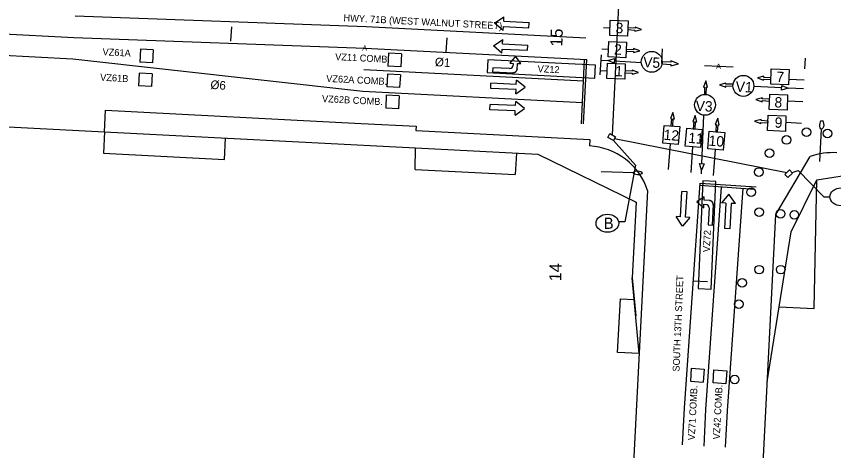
# Model space of a CAD drawing. Extents: x 0 to 1361828, y 0 to 1470398.
# Drawn here: x 683277 to 683656, y 734825.2 to 735026.6 of the extents above; entities that cross this region are included whole.
import ezdxf

# ---------------------------------------------------------------- set-up
doc = ezdxf.new("R2010")
doc.units = 0
for name, color, linetype in [('$', 7, 'Continuous'), ('090338 Base_ROW 3 - R_Horz Alg', 7, 'Continuous'), ('MOT Stage 1', 7, 'Continuous'), ('MOT Stage 1 Lanes', 7, 'Continuous'), ('R_Horz Alg Station', 7, 'Continuous'), ('R_TYPE_A_CURB', 7, 'Continuous'), ('RW-EX', 7, 'Continuous'), ('RW-PR', 7, 'Continuous'), ('SIGNAL-EX', 7, 'Continuous'), ('SIGNAL-PLAN VIEW LABLES', 7, 'Continuous'), ('SIGNAL-PR', 7, 'Continuous'), ('TITEXT', 7, 'Continuous'), ('Video-Zones-pr', 7, 'Continuous')]:
    doc.layers.add(name, color=color, linetype=linetype)

# ---------------------------------------------------------------- blocks, each defined once
blk = doc.blocks.new('SARROW_195')
at = {"layer": 'MOT Stage 1'}
for p, q in [((0, 0), (-6, 0)), ((0, -29.42), (0, 0)), ((-6, -29.42), (-6, 0)), ((-6, -29.42), (-11, -29.42)), ((-3, -39.81), (-11, -29.42)), ((5, -29.42), (-3, -39.81)), ((5, -29.42), (0, -29.42))]:
    blk.add_line(p, q, dxfattribs=at)
blk = doc.blocks.new('SARROW_196')
at = {"layer": 'MOT Stage 1'}
for p, q in [((0, 0), (-6, 0)), ((0, -29.42), (0, 0)), ((-6, -29.42), (-6, 0)), ((-6, -29.42), (-11, -29.42)), ((-3, -39.81), (-11, -29.42)), ((5, -29.42), (-3, -39.81)), ((5, -29.42), (0, -29.42))]:
    blk.add_line(p, q, dxfattribs=at)
blk = doc.blocks.new('SARROW_197')
at = {"layer": 'MOT Stage 1'}
for p, q in [((-6, -29.42), (-6, 0)), ((0, 0), (-6, 0)), ((0, -29.42), (0, 0)), ((-6, -29.42), (-11, -29.42)), ((-3, -39.81), (-11, -29.42)), ((5, -29.42), (-3, -39.81)), ((5, -29.42), (0, -29.42))]:
    blk.add_line(p, q, dxfattribs=at)
blk = doc.blocks.new('SARROW_198')
at = {"layer": 'MOT Stage 1'}
for p, q in [((-6, -29.42), (-6, 0)), ((0, 0), (-6, 0)), ((0, -29.42), (0, 0)), ((-6, -29.42), (-11, -29.42)), ((-3, -39.81), (-11, -29.42)), ((5, -29.42), (-3, -39.81)), ((5, -29.42), (0, -29.42))]:
    blk.add_line(p, q, dxfattribs=at)
blk = doc.blocks.new('SARROW_203')
at = {"layer": 'MOT Stage 1'}
for p, q in [((-6, -29.42), (-6, 0)), ((0, 0), (-6, 0)), ((0, -29.42), (0, 0)), ((-6, -29.42), (-11, -29.42)), ((-3, -39.81), (-11, -29.42)), ((5, -29.42), (-3, -39.81)), ((5, -29.42), (0, -29.42))]:
    blk.add_line(p, q, dxfattribs=at)
blk = doc.blocks.new('SARROW_204')
at = {"layer": 'MOT Stage 1'}
for p, q in [((-6, -29.42), (-6, 0)), ((0, 0), (-6, 0)), ((0, -29.42), (0, 0)), ((-6, -29.42), (-11, -29.42)), ((-3, -39.81), (-11, -29.42)), ((5, -29.42), (-3, -39.81)), ((5, -29.42), (0, -29.42))]:
    blk.add_line(p, q, dxfattribs=at)
blk = doc.blocks.new('BAREL_1730')
at = {"layer": 'MOT Stage 1'}
blk.add_circle((0, 0.01), 2.88, dxfattribs=at)
blk = doc.blocks.new('BAREL_1731')
at = {"layer": 'MOT Stage 1'}
blk.add_circle((0, 0.01), 2.88, dxfattribs=at)
blk = doc.blocks.new('BAREL_1732')
at = {"layer": 'MOT Stage 1'}
blk.add_circle((0, 0.01), 2.88, dxfattribs=at)
blk = doc.blocks.new('BAREL_1733')
at = {"layer": 'MOT Stage 1'}
blk.add_circle((0, 0.01), 2.88, dxfattribs=at)
blk = doc.blocks.new('BAREL_1734')
at = {"layer": 'MOT Stage 1'}
blk.add_circle((0, 0.01), 2.88, dxfattribs=at)
blk = doc.blocks.new('BAREL_1735')
at = {"layer": 'MOT Stage 1'}
blk.add_circle((0, 0.01), 2.88, dxfattribs=at)
blk = doc.blocks.new('BAREL_1736')
at = {"layer": 'MOT Stage 1'}
blk.add_circle((0, 0.01), 2.88, dxfattribs=at)
blk = doc.blocks.new('BAREL_1737')
at = {"layer": 'MOT Stage 1'}
blk.add_circle((0, 0.01), 2.88, dxfattribs=at)
blk = doc.blocks.new('BAREL_1738')
at = {"layer": 'MOT Stage 1'}
blk.add_circle((0, 0.01), 2.88, dxfattribs=at)
blk = doc.blocks.new('BAREL_1739')
at = {"layer": 'MOT Stage 1'}
blk.add_circle((0, 0.01), 2.88, dxfattribs=at)
blk = doc.blocks.new('BAREL_1740')
at = {"layer": 'MOT Stage 1'}
blk.add_circle((0, 0.01), 2.88, dxfattribs=at)
blk = doc.blocks.new('BAREL_1741')
at = {"layer": 'MOT Stage 1'}
blk.add_circle((0, 0.01), 2.88, dxfattribs=at)
blk = doc.blocks.new('BAREL_1742')
at = {"layer": 'MOT Stage 1'}
blk.add_circle((0, 0.01), 2.88, dxfattribs=at)
blk = doc.blocks.new('BAREL_1743')
at = {"layer": 'MOT Stage 1'}
blk.add_circle((0, 0.01), 2.88, dxfattribs=at)

msp = doc.modelspace()

# ---------------------------------------------------------------- linework, layer by layer
at = {"layer": '$'}
for p, q in [((683547.74, 734999.56), (683548.38, 735008.82)), ((683642.77, 735007.23), (683642.46, 735002.24))]:
    msp.add_line(p, q, dxfattribs=at)
at = {"layer": 'MOT Stage 1'}
for points in [[(683509.26, 735002.33), (683509.25, 735002.01), (683509.35, 735004.76), (683510.95, 735004.7), (683508.51, 735008.11), (683505.83, 735004.89), (683507.43, 735004.83), (683507.4, 735004)], [(683505.74, 735002.46), (683497.89, 735002.75), (683497.82, 735000.83)], [(683497.82, 735000.83), (683507.59, 735000.47), (683507.27, 735000.48)], [(683598.36, 734941.28), (683598.68, 734941.27), (683595.93, 734941.39), (683596, 734942.99), (683592.57, 734940.57), (683595.77, 734937.87), (683595.84, 734939.47), (683596.68, 734939.43)], [(683599.78, 734929.83), (683600.21, 734939.6), (683600.19, 734939.28)], [(683598.21, 734937.76), (683597.86, 734929.91), (683599.78, 734929.83)]]:
    msp.add_lwpolyline(points, dxfattribs=at)
for centre, radius, start, end in [((683505.8, 735004.06), 1.6, 267.8614, 357.8614), ((683507.34, 735002.4), 1.92, 267.8614, 357.8614), ((683596.61, 734937.83), 1.6, 357.5178, 87.5178), ((683598.27, 734939.36), 1.92, 357.5178, 87.5178)]:
    msp.add_arc(centre, radius, start, end, dxfattribs=at)
at = {"layer": 'MOT Stage 1 Lanes'}
for p, q in [((683123.62, 735026.19), (683303.69, 735016.89)), ((683304.21, 735026.87), (683439.13, 735021.9)), ((683439.13, 735021.9), (683541.04, 735016.68)), ((683123.1, 735016.21), (683303.18, 735006.9)), ((683303.69, 735016.89), (683438.61, 735011.92)), ((683438.61, 735011.92), (683541.52, 735006.64)), ((683303.18, 735006.9), (683437.59, 734991.94)), ((683538.99, 734976.8), (683540.52, 735006.69)), ((683539.99, 734976.73), (683541.52, 735006.64)), ((683438.1, 735001.93), (683540.01, 734996.7)), ((683437.59, 734991.94), (683539.5, 734986.71)), ((683585.91, 734827.88), (683586.78, 734844.88))]:
    msp.add_line(p, q, dxfattribs=at)
for points in [[(683586.78, 734844.88), (683594.07, 734949.32), (683620.04, 734947.51)], [(683594, 734948.32), (683619.33, 734946.56)], [(683595.89, 734827.37), (683596.76, 734844.27), (683603.97, 734947.63)], [(683605.88, 734826.85), (683606.74, 734843.67), (683613.95, 734946.93)]]:
    msp.add_lwpolyline(points, dxfattribs=at)
at = {"layer": 'R_Horz Alg Station'}
for points in [[(683376.69, 735021.79), (683376.35, 735015.13)], [(683476.56, 735016.64), (683476.22, 735009.99)], [(683576.43, 735011.52), (683576.09, 735004.86)], [(683596.02, 735003.84), (683609.34, 735003.16)], [(683590.9, 734903.97), (683597.56, 734903.63)]]:
    msp.add_lwpolyline(points, dxfattribs=at)
at = {"layer": 'R_TYPE_A_CURB'}
msp.add_lwpolyline([(683564.16, 734940.5), (683564.4, 734940.38), (683562.6, 734905.43), (683564.2, 734887.82)], dxfattribs=at)
at = {"layer": 'RW-EX'}
for p, q in [((683436.82, 734976.96), (683462.39, 734975.65)), ((683462.39, 734975.65), (683462.29, 734973.65)), ((683462.29, 734973.65), (683542.86, 734969.52)), ((683542.86, 734969.52), (683542.71, 734966.52)), ((683629.19, 734934.75), (683645.1, 734961.68)), ((683569.69, 734945.89), (683545.76, 734479.81)), ((683605.66, 734476.49), (683629.19, 734934.75))]:
    msp.add_line(p, q, dxfattribs=at)
msp.add_lwpolyline([(682968.24, 735001.18), (682967.74, 734991.19), (683067.68, 734986.03), (683317.82, 734973.1), (683318.3, 734983.09), (683436.82, 734976.96)], dxfattribs=at)
for centre, radius, start, end in [((683541.17, 734936.56), 30, 18.1182, 87.0636), ((683655.68, 734930.43), 33, 86.7989, 108.7102)]:
    msp.add_arc(centre, radius, start, end, dxfattribs=at)
at = {"layer": 'RW-PR'}
for p, q in [((683317.82, 734973.1), (683317.34, 734963.11)), ((683373.51, 734960.21), (683374.03, 734970.19)), ((683461.97, 734955.65), (683462.1, 734965.65)), ((683317.34, 734963.11), (683373.51, 734960.21)), ((683508.87, 734963.25), (683508.35, 734953.27)), ((683461.97, 734955.65), (683508.35, 734953.27)), ((683646.98, 734891.08), (683648.18, 734950.88)), ((683555.81, 734870.72), (683557.1, 734895.7)), ((683557.1, 734895.7), (683563.52, 734895.37)), ((683630.75, 734891.91), (683646.98, 734891.08)), ((683565.8, 734870.21), (683555.81, 734870.72))]:
    msp.add_line(p, q, dxfattribs=at)
for points in [[(683317.82, 734973.1), (683462.1, 734965.65), (683518.85, 734962.74)], [(683518.85, 734962.74), (683564.4, 734940.38), (683562.6, 734905.43)], [(683648.18, 734950.88), (683683.55, 734956.41), (683823.33, 734948.59), (683952.62, 734938.86), (684206.41, 734924.66)], [(683625.21, 734857.15), (683636.29, 734926.68), (683648.18, 734950.88)], [(683565.8, 734870.21), (683562.6, 734905.43)]]:
    msp.add_lwpolyline(points, dxfattribs=at)
at = {"layer": 'SIGNAL-EX'}
for points in [[(683553.48, 734971.62), (683557.44, 735053.56)], [(683553.94, 734969.07), (683564.03, 734957.59)], [(683554.4, 734969.91), (683634.28, 734954.17)], [(683636.75, 734954.19), (683639.53, 734955.17)]]:
    msp.add_lwpolyline(points, dxfattribs=at)
for points in [[(683552.26, 734972.26), (683554.89, 734970.83), (683553.94, 734969.07), (683551.3, 734970.5)], [(683633.41, 734953.33), (683635.56, 734955.41), (683636.95, 734953.98), (683634.8, 734951.89)]]:
    msp.add_lwpolyline(points, close=True, dxfattribs=at)
at = {"layer": 'SIGNAL-PLAN VIEW LABLES'}
for points in [[(683552.13, 735017.78), (683552.38, 735024.91), (683560.64, 735024.62), (683560.39, 735017.42)], [(683551.42, 735007.8), (683551.67, 735014.93), (683559.93, 735014.65), (683559.68, 735007.45)], [(683551.34, 735006.17), (683554.36, 735007.04), (683554.22, 735004.96)], [(683550.85, 734997.82), (683551.1, 735004.95), (683559.35, 735004.66), (683559.1, 734997.46)], [(683626.81, 734995.16), (683627.06, 735002.29), (683635.31, 735002), (683635.06, 734994.8)], [(683634.84, 734993.33), (683631.82, 734992.45), (683631.95, 734994.53)], [(683626.1, 734983.45), (683626.35, 734990.58), (683634.6, 734990.3), (683634.35, 734983.1)], [(683625.37, 734973.63), (683625.62, 734980.76), (683633.88, 734980.47), (683633.63, 734973.27)], [(683583.86, 734967.24), (683576.75, 734967.85), (683577.45, 734976.08), (683584.63, 734975.47)], [(683594.29, 734965.88), (683587.18, 734966.49), (683587.88, 734974.72), (683595.06, 734974.1)], [(683604.72, 734964.52), (683597.61, 734965.13), (683598.32, 734973.36), (683605.49, 734972.74)], [(683594.76, 734955.33), (683593.84, 734958.34), (683595.92, 734958.24)]]:
    msp.add_lwpolyline(points, close=True, dxfattribs=at)
for points in [[(683549.26, 735021.51), (683552.26, 735021.34)], [(683563.84, 735020.29), (683563.81, 735019.79), (683566.81, 735020.56), (683563.91, 735021.63), (683563.88, 735021.13), (683560.53, 735021.3), (683560.48, 735020.46), (683563.84, 735020.29)], [(683560.48, 735020.46), (683563.84, 735020.29), (683563.81, 735019.79), (683566.81, 735020.56), (683563.91, 735021.63), (683563.88, 735021.13), (683560.53, 735021.3)], [(683548.55, 735011.54), (683551.55, 735011.37)], [(683563.13, 735010.31), (683563.1, 735009.81), (683566.1, 735010.58), (683563.2, 735011.66), (683563.17, 735011.15), (683559.82, 735011.33), (683559.77, 735010.49), (683563.13, 735010.31)], [(683559.77, 735010.49), (683563.13, 735010.31), (683563.1, 735009.81), (683566.1, 735010.58), (683563.2, 735011.66), (683563.17, 735011.15), (683559.82, 735011.33)], [(683548.3, 735006.34), (683551.34, 735006.17)], [(683554.29, 735006), (683566.79, 735005.3)], [(683580.46, 735004.34), (683580.43, 735003.74), (683584.02, 735004.66), (683580.55, 735005.95), (683580.51, 735005.35), (683576.49, 735005.56), (683576.44, 735004.55), (683580.46, 735004.34)], [(683576.44, 735004.55), (683580.46, 735004.34), (683580.43, 735003.74), (683584.02, 735004.66), (683580.55, 735005.95), (683580.51, 735005.35), (683576.49, 735005.56)], [(683547.98, 735001.55), (683550.97, 735001.38)], [(683562.55, 735000.33), (683562.52, 734999.83), (683565.52, 735000.6), (683562.62, 735001.67), (683562.59, 735001.17), (683559.24, 735001.34), (683559.19, 735000.5), (683562.55, 735000.33)], [(683559.19, 735000.5), (683562.55, 735000.33), (683562.52, 734999.83), (683565.52, 735000.6), (683562.62, 735001.67), (683562.59, 735001.17), (683559.24, 735001.34)], [(683597.01, 734993.79), (683597.52, 734993.76), (683596.73, 734996.75), (683595.67, 734993.85), (683596.17, 734993.83), (683596.02, 734990.47), (683596.86, 734990.43), (683597.01, 734993.79)], [(683596.86, 734990.43), (683597.01, 734993.79), (683597.52, 734993.76), (683596.73, 734996.75), (683595.67, 734993.85), (683596.17, 734993.83), (683596.02, 734990.47)], [(683605.96, 734995.2), (683605.97, 734995.71), (683603, 734994.84), (683605.93, 734993.86), (683605.94, 734994.36), (683609.3, 734994.3), (683609.32, 734995.14), (683605.96, 734995.2)], [(683609.32, 734995.14), (683605.96, 734995.2), (683605.97, 734995.71), (683603, 734994.84), (683605.93, 734993.86), (683605.94, 734994.36), (683609.3, 734994.3)], [(683623.57, 734998.34), (683623.59, 734998.85), (683620.6, 734998.08), (683623.5, 734997), (683623.52, 734997.5), (683626.88, 734997.33), (683626.92, 734998.17), (683623.57, 734998.34)], [(683626.92, 734998.17), (683623.57, 734998.34), (683623.59, 734998.85), (683620.6, 734998.08), (683623.5, 734997), (683623.52, 734997.5), (683626.88, 734997.33)], [(683642.24, 734996.96), (683635.13, 734997.33)], [(683631.89, 734993.48), (683618.96, 734994.13)], [(683641.99, 734992.97), (683634.84, 734993.33)], [(683622.89, 734988.36), (683622.92, 734988.87), (683619.93, 734988.1), (683622.82, 734987.02), (683622.85, 734987.53), (683626.2, 734987.35), (683626.25, 734988.19), (683622.89, 734988.36)], [(683626.25, 734988.19), (683622.89, 734988.36), (683622.92, 734988.87), (683619.93, 734988.1), (683622.82, 734987.02), (683622.85, 734987.53), (683626.2, 734987.35)], [(683641.62, 734986.98), (683634.51, 734987.35)], [(683581.62, 734979.1), (683582.12, 734979.06), (683581.43, 734982.07), (683580.28, 734979.2), (683580.78, 734979.16), (683580.52, 734975.81), (683581.36, 734975.75), (683581.62, 734979.1)], [(683581.36, 734975.75), (683581.62, 734979.1), (683582.12, 734979.06), (683581.43, 734982.07), (683580.28, 734979.2), (683580.78, 734979.16), (683580.52, 734975.81)], [(683591.99, 734977.74), (683592.49, 734977.7), (683591.8, 734980.72), (683590.65, 734977.85), (683591.15, 734977.81), (683590.89, 734974.46), (683591.73, 734974.39), (683591.99, 734977.74)], [(683591.73, 734974.39), (683591.99, 734977.74), (683592.49, 734977.7), (683591.8, 734980.72), (683590.65, 734977.85), (683591.15, 734977.81), (683590.89, 734974.46)], [(683594.91, 734958.29), (683595.8, 734980.79)], [(683602.42, 734976.38), (683602.92, 734976.34), (683602.23, 734979.36), (683601.08, 734976.49), (683601.58, 734976.45), (683601.32, 734973.1), (683602.16, 734973.03), (683602.42, 734976.38)], [(683602.16, 734973.03), (683602.42, 734976.38), (683602.92, 734976.34), (683602.23, 734979.36), (683601.08, 734976.49), (683601.58, 734976.45), (683601.32, 734973.1)], [(683622.3, 734978.26), (683622.33, 734978.77), (683619.33, 734978), (683622.23, 734976.92), (683622.26, 734977.43), (683625.61, 734977.25), (683625.66, 734978.09), (683622.3, 734978.26)], [(683625.66, 734978.09), (683622.3, 734978.26), (683622.33, 734978.77), (683619.33, 734978), (683622.23, 734976.92), (683622.26, 734977.43), (683625.61, 734977.25)], [(683641, 734977), (683633.89, 734977.37)], [(683579.47, 734955.58), (683580.3, 734967.55)], [(683589.9, 734954.21), (683590.73, 734966.18)], [(683600.33, 734952.85), (683601.16, 734964.82)], [(683564.03, 734957.59), (683559.2, 734931.31), (683556.26, 734931.31)], [(683594.68, 734953.59), (683594.76, 734955.33)], [(683639.53, 734955.17), (683651.38, 734942.98), (683654.24, 734942.98)], [(683545.85, 734931.31), (683545.78, 734931.31)]]:
    msp.add_lwpolyline(points, dxfattribs=at)
for centre in [(683571.63, 735005.53), (683614.12, 734994.38), (683596.33, 734985.61)]:
    msp.add_circle(centre, 4.85, dxfattribs=at)
for centre in [(683659.51, 734942.94), (683551.06, 734930.68)]:
    msp.add_ellipse(centre, major_axis=(-5.27, 0), ratio=0.790685, dxfattribs=at)
at = {"layer": 'SIGNAL-PR'}
for p, q in [((683649.58, 734959.27), (683650.35, 734974.25)), ((683548.11, 734954.74), (683563.1, 734954.15))]:
    msp.add_line(p, q, dxfattribs=at)
for centre, major_axis in [((683650.46, 734976.27), (-0.11, -2.02)), ((683565.12, 734954.07), (-2.02, 0.08))]:
    msp.add_ellipse(centre, major_axis=major_axis, ratio=0.447722, dxfattribs=at)
at = {"layer": 'Video-Zones-pr'}
for points in [[(683334.49, 735011.34), (683334.18, 735005.34)], [(683340.48, 735011.03), (683334.49, 735011.34)], [(683340.48, 735011.03), (683340.18, 735005.03)], [(683449.55, 735009.49), (683449.24, 735003.5)], [(683455.54, 735009.18), (683449.55, 735009.49)], [(683455.54, 735009.18), (683455.23, 735003.19)], [(683340.18, 735005.03), (683334.18, 735005.34)], [(683455.23, 735003.19), (683449.24, 735003.5)], [(683333.93, 735000.35), (683333.62, 734994.36)], [(683339.92, 735000.04), (683333.93, 735000.35)], [(683339.92, 735000.04), (683339.61, 734994.05)], [(683449.05, 734999.89), (683448.75, 734993.9)], [(683455.05, 734999.58), (683449.05, 734999.89)], [(683455.05, 734999.58), (683454.74, 734993.59)], [(683339.61, 734994.05), (683333.62, 734994.36)], [(683454.74, 734993.59), (683448.75, 734993.9)], [(683448.55, 734990.11), (683448.25, 734984.12)], [(683454.55, 734989.8), (683448.55, 734990.11)], [(683454.55, 734989.8), (683454.24, 734983.81)], [(683454.24, 734983.81), (683448.25, 734984.12)], [(683589.93, 734863.4), (683589.55, 734857.41)], [(683589.93, 734863.4), (683595.91, 734862.98)], [(683595.91, 734862.98), (683595.54, 734857)], [(683600.46, 734862.67), (683606.45, 734862.25), (683606.03, 734856.26), (683600.04, 734856.68), (683600.46, 734862.67)], [(683589.55, 734857.41), (683595.54, 734857)]]:
    msp.add_lwpolyline(points, dxfattribs=at)
for points in [[(683495.35, 735000.52), (683545.29, 734997.96), (683545.6, 735003.95), (683495.66, 735006.51)], [(683595.39, 734950.32), (683593.21, 734900.39), (683599.21, 734900.09), (683601.39, 734950.06)]]:
    msp.add_lwpolyline(points, close=True, dxfattribs=at)

# ---------------------------------------------------------------- block references
at = {"layer": 'MOT Stage 1'}
for name, p, xscale, yscale, rotation in [('SARROW_198', (683514.61, 735021.38), 0.39999999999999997, 0.4, -92.95654264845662), ('SARROW_197', (683514.03, 735010.87), 0.39999999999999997, 0.4, -92.95654264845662), ('SARROW_195', (683496.97, 734993.2), 0.40000000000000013, -0.4000000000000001, -92.4271609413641), ('SARROW_196', (683496.59, 734983.31), 0.40000000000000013, -0.4000000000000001, -92.4271609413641), ('BAREL_1731', (683643.45, 734972.94), 0.6945420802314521, 0.6945420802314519, 87.04179557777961), ('BAREL_1730', (683653.17, 734972.32), 0.6945420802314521, 0.6945420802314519, 87.04179557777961), ('BAREL_1732', (683634.14, 734969.3), 0.6945420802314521, 0.6945420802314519, 87.04179557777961), ('BAREL_1733', (683626.26, 734963.13), 0.6945420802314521, 0.6945420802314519, 87.04179557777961), ('BAREL_1734', (683621.33, 734954.43), 0.6945420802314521, 0.6945420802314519, 87.04179557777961), ('BAREL_1735', (683617.68, 734945.12), 0.6945420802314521, 0.6945420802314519, 87.04179557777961), ('SARROW_203', (683587.98, 734945.23), 0.4, 0.39999999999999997, -3.300150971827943), ('SARROW_204', (683607.84, 734928.16), 0.40000000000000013, -0.4000000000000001, -2.7707692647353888), ('BAREL_1736', (683621.44, 734935.85), 0.6945420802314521, 0.6945420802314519, 87.04179557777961), ('BAREL_1737', (683631.4, 734935.05), 0.6945420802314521, 0.6945420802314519, 87.04179557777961), ('BAREL_1738', (683637.76, 734934.56), 0.6945420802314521, 0.6945420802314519, 87.04179557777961), ('BAREL_1740', (683621.43, 734909.16), 0.6945420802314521, 0.6945420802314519, 87.04179557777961), ('BAREL_1739', (683631.43, 734909.16), 0.6945420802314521, 0.6945420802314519, 87.04179557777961), ('BAREL_1741', (683613.52, 734903.03), 0.6945420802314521, 0.6945420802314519, 87.04179557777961), ('BAREL_1742', (683612.03, 734893.14), 0.6945420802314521, 0.6945420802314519, 87.04179557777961), ('BAREL_1743', (683610.09, 734858.2), 0.6945420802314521, 0.6945420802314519, 87.04179557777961)]:
    msp.add_blockref(name, p, dxfattribs=dict(at, xscale=xscale, yscale=yscale, rotation=rotation))

# ---------------------------------------------------------------- texts
at = {"layer": '$'}
for s, height, rotation, p in [('HWY. 71B (WEST WALNUT STREET)', 3.2, 357.0637, (683428.62, 735024.4)), ('15', 5.6, 88.3887, (683530.18, 735012.55)), ('VZ61A', 3.2, 357.0415, (683316.89, 735008.63)), ('VZ11 COMB.', 3.2, 357.0415, (683424.75, 735006.37)), (' VZ12', 3.2, 357.0415, (683517.43, 735000.85)), ('VZ61B', 3.2, 357.0415, (683315.79, 734996.8)), ('VZ62A COMB.', 3.2, 357.0415, (683420.61, 734996.28)), (' VZ62B COMB.', 3.2, 357.0415, (683417.47, 734986.96)), ('VZ72', 3.2, 87.0608, (683598.53, 734917.19)), ('14', 5.6, 88.3887, (683529.62, 734903.72)), ('SOUTH 13TH STREET', 3.2, 87.5995, (683584.49, 734861.81)), ('VZ42 COMB.', 3.2, 87.0608, (683603.16, 734830.34)), ('VZ71 COMB.', 3.2, 87.0608, (683591.56, 734829.97))]:
    msp.add_text(s, height=height, rotation=rotation, dxfattribs=at).set_placement(p)
at = {"layer": '090338 Base_ROW 3 - R_Horz Alg'}
for rotation, p in [(357.0526, (683437.36, 735010.78)), (356.9312, (683601.43, 735002.37))]:
    msp.add_text('A', height=2.4, rotation=rotation, dxfattribs=at).set_placement(p)
at = {"layer": 'SIGNAL-PLAN VIEW LABLES'}
for s, rotation, p in [('3', 357.0414, (683554.76, 735018.91)), ('2', 357.0414, (683554.05, 735008.93)), ('V5', 357.0414, (683567.56, 735003.08)), ('1', 357.0414, (683554.51, 734998.9)), ('7', 357.0414, (683629.35, 734996.24)), ('V1', 357.0414, (683610.45, 734991.69)), ('8', 357.0414, (683628.44, 734984.46)), ('V3', 357.0414, (683591.87, 734982.8)), ('9', 357.0414, (683628.52, 734975.05)), ('12', 355.5482, (683576.99, 734969.42)), ('11', 355.5482, (683588.44, 734967.98)), ('10', 355.5482, (683597.85, 734966.7))]:
    msp.add_text(s, height=4.8, rotation=rotation, dxfattribs=at).set_placement(p)
msp.add_text('B', height=5.2, dxfattribs=at).set_placement((683549.33, 734928.08))
at = {"layer": 'TITEXT'}
for s, p in [('%%C1', (683470.97, 735003.57)), ('%%C6', (683366.89, 734993.02))]:
    msp.add_text(s, height=4, rotation=356.2723, dxfattribs=at).set_placement(p)

doc.saveas('drawing.dxf')
